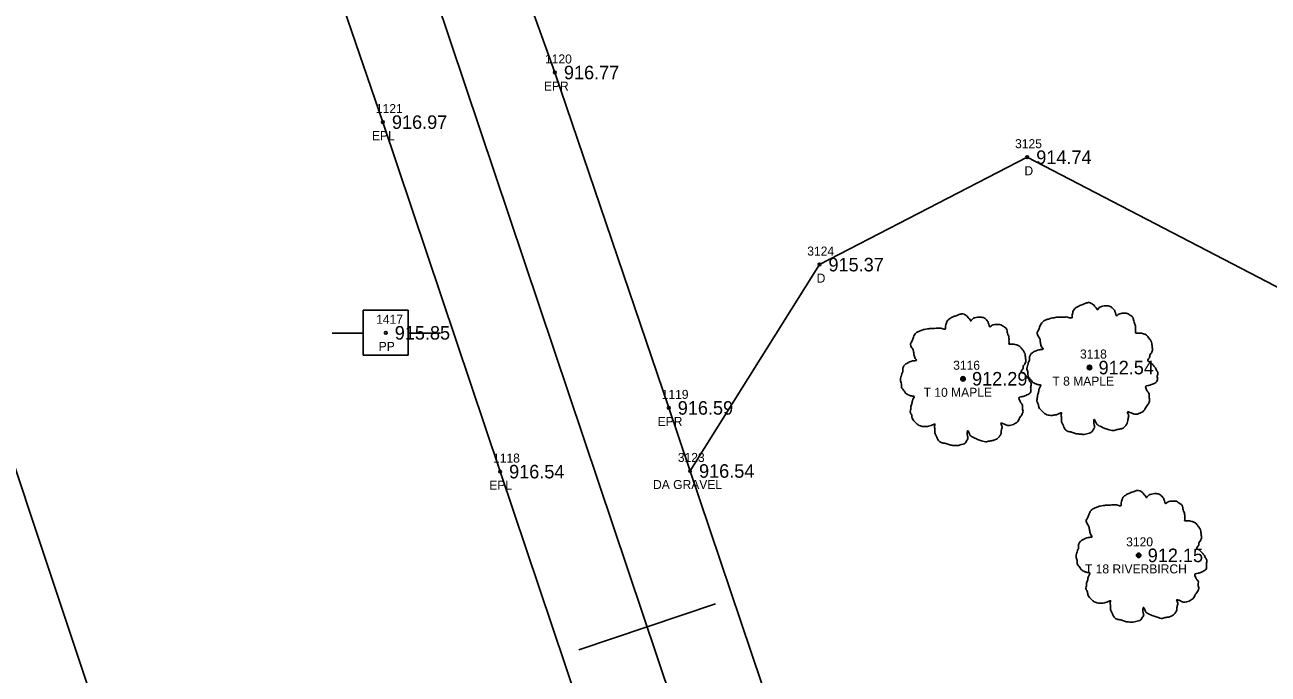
# Model space of a CAD drawing. Extents: x 1528109 to 1531398, y 1157799 to 1162548.
# Drawn here: x 1529638.1 to 1529775.9, y 1160096.9 to 1160168.9 of the extents above; entities that cross this region are included whole.
import ezdxf

# ---------------------------------------------------------------- set-up
doc = ezdxf.new("R2010")
doc.units = 0
for name, color, linetype in [('RD_EX_Driveway', 7, 'Continuous'), ('RD_EX_Driveway_txCode', 7, 'Continuous'), ('RD_EX_Road', 7, 'Continuous'), ('RD_EX_Road_txCode', 7, 'Continuous'), ('RD_EX_TX_Driveway_ELEV', 7, 'Continuous'), ('RD_EX_TX_Road_ELEV', 7, 'Continuous'), ('RD_EX_TX_VEG_ELEV', 7, 'Continuous'), ('RD_EX_UT', 7, 'Continuous'), ('RD_EX_UT_txCode', 7, 'Continuous'), ('RD_EX_VEG', 7, 'Continuous'), ('RD_EX_VEG_txCode', 7, 'Continuous'), ('RD_HC_Cl', 7, 'Continuous'), ('RD_HC_Data_Tic', 7, 'Continuous'), ('RD_HC_Survey_ELEV', 7, 'Continuous'), ('RD_SMD_Locator', 7, 'Continuous')]:
    doc.layers.add(name, color=color, linetype=linetype)

msp = doc.modelspace()

# ---------------------------------------------------------------- linework, layer by layer
at = {"layer": 'RD_EX_Driveway'}
msp.add_lwpolyline([(1529711.85, 1160119.44), (1529726.2, 1160142.31), (1529749.24, 1160154.21), (1529805.14, 1160125.19), (1529809.72, 1160131.73), (1529839.15, 1160123.99)], dxfattribs=at)
at = {"layer": 'RD_EX_Road'}
for points in [[(1529774.72, 1159933.62), (1529755.68, 1159989.25), (1529731.24, 1160061.98), (1529709.49, 1160126.43), (1529696.87, 1160163.6), (1529690.11, 1160182.42), (1529676.19, 1160223.82)], [(1529755.29, 1159927.01), (1529736.93, 1159982.35), (1529712.51, 1160054.89), (1529690.79, 1160119.37), (1529677.8, 1160158.1), (1529657.44, 1160217.45)]]:
    msp.add_lwpolyline(points, dxfattribs=at)
at = {"layer": 'RD_EX_UT'}
for p, q in [((1529680.6, 1160137.26), (1529675.6, 1160137.26)), ((1529675.6, 1160137.26), (1529675.6, 1160132.26)), ((1529680.6, 1160132.26), (1529680.6, 1160137.26)), ((1529672.17, 1160134.7), (1529675.64, 1160134.7)), ((1529680.53, 1160134.7), (1529684.17, 1160134.7)), ((1529675.6, 1160132.26), (1529680.6, 1160132.26))]:
    msp.add_line(p, q, dxfattribs=at)
at = {"layer": 'RD_EX_VEG'}
msp.add_lwpolyline([(1529518.34, 1160217.08), (1529606.49, 1160211.39), (1529711.98, 1159894.63), (1529689.16, 1159889.01)], dxfattribs=at)
for centre, radius in [((1529756.15, 1160130.9), 0.25), ((1529742.12, 1160129.66), 0.25), ((1529742.1, 1160129.64), 0.0001), ((1529756.14, 1160130.89), 0.0001), ((1529761.6, 1160110.09), 0.25), ((1529761.58, 1160110.07), 0.0001)]:
    msp.add_circle(centre, radius, dxfattribs=at)
for points in [[(1529756.28, 1160138.07), (1529755.99, 1160138.1), (1529755.66, 1160138), (1529755.41, 1160137.9), (1529755.19, 1160137.82), (1529754.96, 1160137.72), (1529754.66, 1160137.55), (1529754.44, 1160137.35), (1529754.31, 1160137.1), (1529754.26, 1160136.87), (1529754.21, 1160136.6), (1529754.21, 1160136.42), (1529754.09, 1160136.4), (1529753.94, 1160136.42), (1529753.69, 1160136.5), (1529753.44, 1160136.5), (1529753.19, 1160136.5), (1529752.84, 1160136.47), (1529752.49, 1160136.47), (1529752.21, 1160136.42), (1529751.89, 1160136.37), (1529751.51, 1160136.25), (1529751.16, 1160136.12), (1529750.86, 1160135.87), (1529750.61, 1160135.4), (1529750.49, 1160135.05), (1529750.34, 1160134.8), (1529750.49, 1160134.35), (1529750.66, 1160134), (1529750.69, 1160133.8), (1529750.76, 1160133.37), (1529750.86, 1160133.15), (1529750.99, 1160132.95), (1529750.91, 1160132.92), (1529750.54, 1160132.87), (1529750.24, 1160132.77), (1529749.81, 1160132.55), (1529749.59, 1160132.32), (1529749.49, 1160132), (1529749.46, 1160131.65), (1529749.36, 1160131.45), (1529749.29, 1160131.17), (1529749.26, 1160131.1), (1529749.21, 1160130.77), (1529749.31, 1160130.32), (1529749.34, 1160129.97), (1529749.46, 1160129.75), (1529749.61, 1160129.58), (1529749.79, 1160129.33), (1529750.19, 1160129.1), (1529750.51, 1160129), (1529750.71, 1160128.98), (1529750.54, 1160128.48), (1529750.49, 1160128.13), (1529750.36, 1160127.73), (1529750.36, 1160127.65), (1529750.31, 1160127.18), (1529750.46, 1160126.85), (1529750.54, 1160126.48), (1529750.71, 1160126.25), (1529750.99, 1160125.95), (1529751.31, 1160125.73), (1529751.81, 1160125.6), (1529752.21, 1160125.63), (1529752.79, 1160125.8), (1529753.04, 1160125.88), (1529753.01, 1160125.7), (1529753.04, 1160125.33), (1529753.04, 1160124.9), (1529753.19, 1160124.58), (1529753.29, 1160124.3), (1529753.44, 1160124.05), (1529753.76, 1160123.83), (1529754.16, 1160123.75), (1529754.59, 1160123.6), (1529755.04, 1160123.53), (1529755.54, 1160123.5), (1529756.14, 1160123.65), (1529756.41, 1160123.78), (1529756.51, 1160123.95), (1529756.71, 1160124.33), (1529756.66, 1160124.55), (1529756.68, 1160125.15), (1529756.78, 1160124.98), (1529756.96, 1160124.63), (1529757.46, 1160124.33), (1529757.86, 1160124.15), (1529758.33, 1160124), (1529758.63, 1160123.93), (1529759.11, 1160124), (1529759.48, 1160124.08), (1529759.86, 1160124.2), (1529760.16, 1160124.48), (1529760.33, 1160124.75), (1529760.38, 1160125.03), (1529760.46, 1160125.4), (1529760.51, 1160125.58)], [(1529760.51, 1160125.58), (1529760.43, 1160125.75), (1529760.38, 1160126), (1529760.46, 1160125.98), (1529760.63, 1160125.93), (1529760.91, 1160125.8), (1529761.13, 1160125.73), (1529761.46, 1160125.75), (1529761.73, 1160125.85), (1529762.18, 1160126.13), (1529762.46, 1160126.6), (1529762.73, 1160127), (1529762.81, 1160127.33), (1529762.76, 1160127.55), (1529762.73, 1160128.05), (1529762.53, 1160128.3), (1529762.48, 1160128.43), (1529762.38, 1160128.83), (1529762.46, 1160128.88), (1529762.73, 1160128.93), (1529763.11, 1160129.05), (1529763.38, 1160129.18), (1529763.61, 1160129.35), (1529763.68, 1160129.58), (1529763.66, 1160129.97), (1529763.71, 1160130.37), (1529763.63, 1160130.52), (1529763.53, 1160130.67), (1529763.46, 1160130.87), (1529763.31, 1160131.02), (1529763.21, 1160131.17), (1529763.11, 1160131.27), (1529762.98, 1160131.42), (1529762.81, 1160131.55), (1529762.66, 1160131.6), (1529762.61, 1160131.75), (1529762.76, 1160131.95), (1529762.81, 1160132.05), (1529762.83, 1160132.27), (1529763.06, 1160132.62), (1529763.11, 1160133.02), (1529763.06, 1160133.45), (1529763.01, 1160133.72), (1529762.86, 1160134), (1529762.66, 1160134.25), (1529762.53, 1160134.42), (1529762.36, 1160134.55), (1529762.03, 1160134.67), (1529761.78, 1160134.72), (1529761.43, 1160134.72), (1529761.23, 1160134.77), (1529761.26, 1160134.82), (1529761.26, 1160134.97), (1529761.26, 1160135.25), (1529761.18, 1160135.7), (1529761.03, 1160136.2), (1529761.03, 1160136.22), (1529760.93, 1160136.47), (1529760.71, 1160136.67), (1529760.53, 1160136.77), (1529760.33, 1160136.9), (1529760.08, 1160136.92), (1529759.78, 1160136.92), (1529759.51, 1160136.87), (1529759.31, 1160136.77), (1529759.13, 1160136.65), (1529759.06, 1160136.8), (1529758.96, 1160137.1), (1529758.91, 1160137.25), (1529758.76, 1160137.42), (1529758.53, 1160137.62), (1529758.08, 1160137.75), (1529757.46, 1160137.67), (1529757.16, 1160137.47), (1529757.01, 1160137.3), (1529756.96, 1160137.42), (1529756.76, 1160137.62), (1529756.66, 1160137.8), (1529756.48, 1160137.92), (1529756.33, 1160138.02), (1529756.23, 1160138.07)], [(1529742.25, 1160136.83), (1529741.95, 1160136.85), (1529741.62, 1160136.75), (1529741.37, 1160136.65), (1529741.15, 1160136.58), (1529740.92, 1160136.48), (1529740.62, 1160136.3), (1529740.4, 1160136.1), (1529740.27, 1160135.85), (1529740.22, 1160135.63), (1529740.17, 1160135.35), (1529740.17, 1160135.18), (1529740.05, 1160135.15), (1529739.9, 1160135.18), (1529739.65, 1160135.25), (1529739.4, 1160135.25), (1529739.15, 1160135.25), (1529738.8, 1160135.23), (1529738.45, 1160135.23), (1529738.17, 1160135.18), (1529737.85, 1160135.13), (1529737.47, 1160135), (1529737.12, 1160134.88), (1529736.83, 1160134.63), (1529736.58, 1160134.15), (1529736.45, 1160133.8), (1529736.3, 1160133.55), (1529736.45, 1160133.1), (1529736.63, 1160132.75), (1529736.65, 1160132.55), (1529736.73, 1160132.13), (1529736.83, 1160131.9), (1529736.95, 1160131.7), (1529736.88, 1160131.68), (1529736.5, 1160131.63), (1529736.2, 1160131.53), (1529735.78, 1160131.3), (1529735.55, 1160131.08), (1529735.45, 1160130.75), (1529735.43, 1160130.4), (1529735.33, 1160130.2), (1529735.25, 1160129.93), (1529735.23, 1160129.85), (1529735.18, 1160129.53), (1529735.28, 1160129.08), (1529735.3, 1160128.73), (1529735.43, 1160128.5), (1529735.58, 1160128.33), (1529735.75, 1160128.08), (1529736.15, 1160127.85), (1529736.48, 1160127.75), (1529736.68, 1160127.73), (1529736.5, 1160127.23), (1529736.45, 1160126.88), (1529736.33, 1160126.48), (1529736.33, 1160126.41), (1529736.28, 1160125.93), (1529736.43, 1160125.61), (1529736.5, 1160125.23), (1529736.68, 1160125.01), (1529736.95, 1160124.71), (1529737.27, 1160124.48), (1529737.77, 1160124.36), (1529738.17, 1160124.38), (1529738.75, 1160124.56), (1529739, 1160124.63), (1529738.97, 1160124.46), (1529739, 1160124.08), (1529739, 1160123.66), (1529739.15, 1160123.33), (1529739.25, 1160123.06), (1529739.4, 1160122.81), (1529739.72, 1160122.58), (1529740.12, 1160122.51), (1529740.55, 1160122.36), (1529741, 1160122.28), (1529741.5, 1160122.26), (1529742.1, 1160122.41), (1529742.37, 1160122.53), (1529742.47, 1160122.71), (1529742.67, 1160123.08), (1529742.62, 1160123.31), (1529742.65, 1160123.91), (1529742.75, 1160123.73), (1529742.92, 1160123.38), (1529743.42, 1160123.08), (1529743.82, 1160122.91), (1529744.3, 1160122.76), (1529744.6, 1160122.68), (1529745.07, 1160122.76), (1529745.45, 1160122.83), (1529745.82, 1160122.96), (1529746.12, 1160123.23), (1529746.3, 1160123.51), (1529746.35, 1160123.78), (1529746.42, 1160124.16), (1529746.47, 1160124.33)], [(1529746.47, 1160124.33), (1529746.4, 1160124.51), (1529746.35, 1160124.76), (1529746.42, 1160124.73), (1529746.6, 1160124.68), (1529746.87, 1160124.56), (1529747.1, 1160124.48), (1529747.42, 1160124.51), (1529747.7, 1160124.61), (1529748.15, 1160124.88), (1529748.42, 1160125.36), (1529748.69, 1160125.76), (1529748.77, 1160126.08), (1529748.72, 1160126.31), (1529748.69, 1160126.8), (1529748.49, 1160127.05), (1529748.44, 1160127.18), (1529748.35, 1160127.58), (1529748.42, 1160127.63), (1529748.69, 1160127.68), (1529749.07, 1160127.8), (1529749.34, 1160127.93), (1529749.57, 1160128.1), (1529749.64, 1160128.33), (1529749.62, 1160128.73), (1529749.67, 1160129.13), (1529749.59, 1160129.28), (1529749.49, 1160129.43), (1529749.42, 1160129.63), (1529749.27, 1160129.78), (1529749.17, 1160129.93), (1529749.07, 1160130.03), (1529748.94, 1160130.18), (1529748.77, 1160130.3), (1529748.62, 1160130.35), (1529748.57, 1160130.5), (1529748.72, 1160130.7), (1529748.77, 1160130.8), (1529748.79, 1160131.03), (1529749.02, 1160131.38), (1529749.07, 1160131.78), (1529749.02, 1160132.2), (1529748.97, 1160132.48), (1529748.82, 1160132.75), (1529748.62, 1160133), (1529748.49, 1160133.18), (1529748.32, 1160133.3), (1529748, 1160133.43), (1529747.75, 1160133.48), (1529747.4, 1160133.48), (1529747.2, 1160133.53), (1529747.22, 1160133.58), (1529747.22, 1160133.73), (1529747.22, 1160134), (1529747.15, 1160134.45), (1529747, 1160134.95), (1529747, 1160134.98), (1529746.9, 1160135.23), (1529746.67, 1160135.43), (1529746.5, 1160135.53), (1529746.3, 1160135.65), (1529746.05, 1160135.68), (1529745.75, 1160135.68), (1529745.47, 1160135.63), (1529745.27, 1160135.53), (1529745.1, 1160135.4), (1529745.02, 1160135.55), (1529744.92, 1160135.85), (1529744.87, 1160136), (1529744.72, 1160136.18), (1529744.5, 1160136.38), (1529744.05, 1160136.5), (1529743.42, 1160136.43), (1529743.12, 1160136.23), (1529742.97, 1160136.05), (1529742.92, 1160136.18), (1529742.72, 1160136.38), (1529742.62, 1160136.55), (1529742.45, 1160136.68), (1529742.3, 1160136.78), (1529742.2, 1160136.83)], [(1529761.73, 1160117.25), (1529761.43, 1160117.28), (1529761.1, 1160117.18), (1529760.85, 1160117.08), (1529760.63, 1160117), (1529760.4, 1160116.9), (1529760.1, 1160116.73), (1529759.88, 1160116.53), (1529759.75, 1160116.28), (1529759.7, 1160116.05), (1529759.65, 1160115.78), (1529759.65, 1160115.6), (1529759.53, 1160115.58), (1529759.38, 1160115.6), (1529759.13, 1160115.68), (1529758.88, 1160115.68), (1529758.63, 1160115.68), (1529758.28, 1160115.65), (1529757.93, 1160115.65), (1529757.66, 1160115.6), (1529757.33, 1160115.55), (1529756.96, 1160115.43), (1529756.61, 1160115.3), (1529756.31, 1160115.05), (1529756.06, 1160114.58), (1529755.93, 1160114.23), (1529755.78, 1160113.98), (1529755.93, 1160113.53), (1529756.11, 1160113.18), (1529756.13, 1160112.98), (1529756.21, 1160112.56), (1529756.31, 1160112.33), (1529756.43, 1160112.13), (1529756.36, 1160112.11), (1529755.98, 1160112.06), (1529755.68, 1160111.96), (1529755.26, 1160111.73), (1529755.03, 1160111.51), (1529754.93, 1160111.18), (1529754.91, 1160110.83), (1529754.81, 1160110.63), (1529754.73, 1160110.36), (1529754.71, 1160110.28), (1529754.66, 1160109.96), (1529754.76, 1160109.51), (1529754.78, 1160109.16), (1529754.91, 1160108.93), (1529755.06, 1160108.76), (1529755.23, 1160108.51), (1529755.63, 1160108.28), (1529755.96, 1160108.18), (1529756.16, 1160108.16), (1529755.98, 1160107.66), (1529755.93, 1160107.31), (1529755.81, 1160106.91), (1529755.81, 1160106.83), (1529755.76, 1160106.36), (1529755.91, 1160106.03), (1529755.98, 1160105.66), (1529756.16, 1160105.43), (1529756.43, 1160105.13), (1529756.76, 1160104.91), (1529757.26, 1160104.78), (1529757.66, 1160104.81), (1529758.23, 1160104.98), (1529758.48, 1160105.06), (1529758.45, 1160104.88), (1529758.48, 1160104.51), (1529758.48, 1160104.08), (1529758.63, 1160103.76), (1529758.73, 1160103.49), (1529758.88, 1160103.24), (1529759.2, 1160103.01), (1529759.6, 1160102.94), (1529760.03, 1160102.79), (1529760.48, 1160102.71), (1529760.98, 1160102.69), (1529761.58, 1160102.84), (1529761.85, 1160102.96), (1529761.95, 1160103.14), (1529762.15, 1160103.51), (1529762.1, 1160103.73), (1529762.13, 1160104.33), (1529762.23, 1160104.16), (1529762.4, 1160103.81), (1529762.9, 1160103.51), (1529763.3, 1160103.34), (1529763.78, 1160103.19), (1529764.08, 1160103.11), (1529764.55, 1160103.19), (1529764.93, 1160103.26), (1529765.3, 1160103.39), (1529765.6, 1160103.66), (1529765.78, 1160103.93), (1529765.83, 1160104.21), (1529765.9, 1160104.58), (1529765.95, 1160104.76)], [(1529765.95, 1160104.76), (1529765.88, 1160104.93), (1529765.83, 1160105.18), (1529765.9, 1160105.16), (1529766.08, 1160105.11), (1529766.35, 1160104.98), (1529766.58, 1160104.91), (1529766.9, 1160104.93), (1529767.18, 1160105.03), (1529767.63, 1160105.31), (1529767.9, 1160105.78), (1529768.18, 1160106.18), (1529768.25, 1160106.51), (1529768.2, 1160106.73), (1529768.18, 1160107.23), (1529767.98, 1160107.48), (1529767.93, 1160107.61), (1529767.83, 1160108.01), (1529767.9, 1160108.06), (1529768.18, 1160108.11), (1529768.55, 1160108.23), (1529768.83, 1160108.36), (1529769.05, 1160108.53), (1529769.13, 1160108.76), (1529769.1, 1160109.16), (1529769.15, 1160109.56), (1529769.08, 1160109.71), (1529768.98, 1160109.86), (1529768.9, 1160110.06), (1529768.75, 1160110.21), (1529768.65, 1160110.36), (1529768.55, 1160110.46), (1529768.43, 1160110.61), (1529768.25, 1160110.73), (1529768.1, 1160110.78), (1529768.05, 1160110.93), (1529768.2, 1160111.13), (1529768.25, 1160111.23), (1529768.28, 1160111.46), (1529768.5, 1160111.81), (1529768.55, 1160112.21), (1529768.5, 1160112.63), (1529768.45, 1160112.91), (1529768.3, 1160113.18), (1529768.1, 1160113.43), (1529767.98, 1160113.61), (1529767.8, 1160113.73), (1529767.48, 1160113.86), (1529767.23, 1160113.91), (1529766.88, 1160113.91), (1529766.68, 1160113.96), (1529766.7, 1160114.01), (1529766.7, 1160114.16), (1529766.7, 1160114.43), (1529766.63, 1160114.88), (1529766.48, 1160115.38), (1529766.48, 1160115.4), (1529766.38, 1160115.65), (1529766.15, 1160115.85), (1529765.98, 1160115.95), (1529765.78, 1160116.08), (1529765.53, 1160116.1), (1529765.23, 1160116.1), (1529764.95, 1160116.05), (1529764.75, 1160115.95), (1529764.58, 1160115.83), (1529764.5, 1160115.98), (1529764.4, 1160116.28), (1529764.35, 1160116.43), (1529764.2, 1160116.6), (1529763.98, 1160116.8), (1529763.53, 1160116.93), (1529762.9, 1160116.85), (1529762.6, 1160116.65), (1529762.45, 1160116.48), (1529762.4, 1160116.6), (1529762.2, 1160116.8), (1529762.1, 1160116.98), (1529761.93, 1160117.1), (1529761.78, 1160117.2), (1529761.68, 1160117.25)]]:
    msp.add_spline(points, degree=3, dxfattribs=at)
at = {"layer": 'RD_HC_Cl'}
msp.add_line((1529913.5, 1159487.74), (1529527.85, 1160635.77), dxfattribs=at)
at = {"layer": 'RD_HC_Data_Tic'}
for q in [(1529714.68, 1160104.72), (1529699.51, 1160099.63)]:
    msp.add_line((1529707.1, 1160102.18), q, dxfattribs=at)
at = {"layer": 'RD_SMD_Locator'}
for centre in [(1529696.87, 1160163.6), (1529677.8, 1160158.1), (1529749.24, 1160154.21), (1529726.2, 1160142.31), (1529678.11, 1160134.75), (1529756.15, 1160130.9), (1529742.12, 1160129.66), (1529709.49, 1160126.43), (1529690.79, 1160119.37), (1529711.85, 1160119.44), (1529761.6, 1160110.09)]:
    msp.add_circle(centre, 0.15, dxfattribs=at)

# ---------------------------------------------------------------- texts
at = {"layer": 'RD_EX_Driveway_txCode'}
for s, p in [('3125', (1529747.89, 1160155.21)), ('D', (1529748.93, 1160152.21)), ('3124', (1529724.85, 1160143.31)), ('D', (1529725.89, 1160140.31)), ('3123', (1529710.5, 1160120.44)), ('DA GRAVEL', (1529707.75, 1160117.44))]:
    msp.add_text(s, height=1, dxfattribs=at).set_placement(p)
at = {"layer": 'RD_EX_Road_txCode'}
for s, p in [('1120', (1529695.77, 1160164.6)), ('EPR', (1529695.65, 1160161.6)), ('1121', (1529677.02, 1160159.1)), ('EPL', (1529676.59, 1160156.1)), ('1119', (1529708.71, 1160127.43)), ('EPR', (1529708.26, 1160124.43)), ('1118', (1529690.01, 1160120.37)), ('EPL', (1529689.59, 1160117.37))]:
    msp.add_text(s, height=1, dxfattribs=at).set_placement(p)
at = {"layer": 'RD_EX_TX_Driveway_ELEV'}
for s, p in [('914.74', (1529750.24, 1160153.46)), ('915.37', (1529727.2, 1160141.56)), ('916.54', (1529712.85, 1160118.69))]:
    msp.add_text(s, height=1.5, dxfattribs=at).set_placement(p)
at = {"layer": 'RD_EX_TX_Road_ELEV'}
for s, p in [('916.77', (1529697.87, 1160162.85)), ('916.97', (1529678.8, 1160157.35)), ('916.59', (1529710.49, 1160125.68)), ('916.54', (1529691.79, 1160118.62))]:
    msp.add_text(s, height=1.5, dxfattribs=at).set_placement(p)
at = {"layer": 'RD_EX_TX_VEG_ELEV'}
for s, p in [('912.54', (1529757.15, 1160130.15)), ('912.29', (1529743.12, 1160128.91)), ('912.15', (1529762.6, 1160109.34))]:
    msp.add_text(s, height=1.5, dxfattribs=at).set_placement(p)
at = {"layer": 'RD_EX_UT_txCode'}
for s, p in [('1417', (1529677.05, 1160135.75)), ('PP', (1529677.33, 1160132.75))]:
    msp.add_text(s, height=1, dxfattribs=at).set_placement(p)
at = {"layer": 'RD_EX_VEG_txCode'}
for s, p in [('3118', (1529755.09, 1160131.9)), ('3116', (1529741.03, 1160130.66)), ('T 8 MAPLE', (1529752.03, 1160128.9)), ('T 10 MAPLE', (1529737.75, 1160127.66)), ('3120', (1529760.21, 1160111.09)), ('T 18 RIVERBIRCH', (1529755.64, 1160108.09))]:
    msp.add_text(s, height=1, dxfattribs=at).set_placement(p)
at = {"layer": 'RD_HC_Survey_ELEV'}
msp.add_text('915.85', height=1.5, dxfattribs=at).set_placement((1529679.11, 1160134))

doc.saveas('drawing.dxf')
